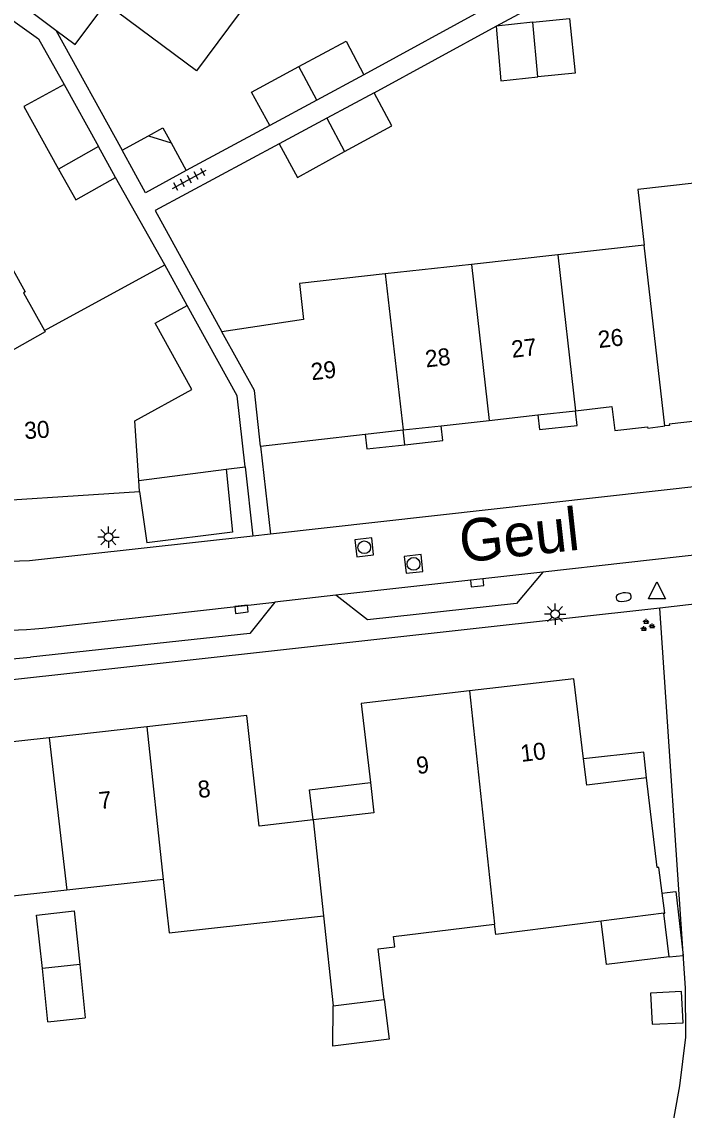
# Model space of a CAD drawing. Extents: x 131000 to 133013, y 393000 to 396501.
# Drawn here: x 131038.3 to 131077.2, y 394996 to 395059.9 of the extents above; entities that cross this region are included whole.
import ezdxf

# ---------------------------------------------------------------- set-up
doc = ezdxf.new("R2010")
doc.units = 0
for name, color, linetype in [('gg-afsc-erfafscheiding', 7, 'Continuous'), ('gg-afsc-muur', 7, 'Continuous'), ('gg-anno-huisnummerreeks BGT', 7, 'Continuous'), ('gg-anno-openbare ruimte label', 7, 'Continuous'), ('gg-bbg-bijgebouw', 7, 'Continuous'), ('gg-bbg-gedigitaliseerde bebouwing', 7, 'Continuous'), ('gg-bbg-gedigitaliseerde bijgebouw', 7, 'Continuous'), ('gg-bbg-hoofdgebouw', 7, 'Continuous'), ('gg-bbg-luifel en loopbrug', 7, 'Continuous'), ('gg-bbg-tussenscheiding', 7, 'Continuous'), ('gg-knt-verharding', 7, 'Continuous'), ('gg-knt-verharding nz', 7, 'Continuous'), ('gt-grn-weggrens', 7, 'Continuous'), ('gt-symb-brandkraan', 7, 'Continuous'), ('gt-symb-groenvak', 7, 'Continuous'), ('gt-symb-kolk', 7, 'Continuous'), ('gt-symb-lichtmast', 7, 'Continuous'), ('gt-symb-rioolschacht', 7, 'Continuous'), ('gt-symb-tegel verharding', 7, 'Continuous'), ('gt-symb-waterafsluiter', 7, 'Continuous')]:
    doc.layers.add(name, color=color, linetype=linetype)

# ---------------------------------------------------------------- blocks, each defined once
blk = doc.blocks.new('gt0-TEG1')
at = {"layer": 'gt-symb-tegel verharding'}
for p, q in [((-1.125, 0), (1.125, 0)), ((-0.9, -0.25), (-0.9, 0.25)), ((-0.45, -0.25), (-0.45, 0.25)), ((0, -0.25), (0, 0.25)), ((0.45, -0.25), (0.45, 0.25)), ((0.9, -0.25), (0.9, 0.25))]:
    blk.add_line(p, q, dxfattribs=at)
blk = doc.blocks.new('gt0-LMAST')
at = {"layer": 'gt-symb-lichtmast'}
for p, q in [((-0.182, 0.173), (-0.447, 0.438)), ((-0.005, 0.246), (-0.005, 0.621)), ((0.172, 0.173), (0.437, 0.438)), ((-0.255, -0.004), (-0.63, -0.004)), ((-0.182, -0.181), (-0.447, -0.446)), ((-0.005, -0.254), (-0.005, -0.629)), ((0.437, -0.446), (0.172, -0.181)), ((0.245, -0.004), (0.62, -0.004))]:
    blk.add_line(p, q, dxfattribs=at)
blk.add_circle((-0.005, -0.004), 0.25, dxfattribs=at)
blk = doc.blocks.new('gt0-KOLK')
at = {"layer": 'gt-symb-kolk'}
blk.add_lwpolyline([(0, 0), (0.375, 0), (0.375, 0.4), (-0.375, 0.4), (-0.375, 0), (0, 0)], dxfattribs=at)
blk = doc.blocks.new('gt0-GRVAK')
at = {"layer": 'gt-symb-groenvak'}
for p, q in [((-0.11, 0.189), (-0.228, 0.24)), ((-0.182, 0.153), (0.088, 0.153)), ((-0.091, 0.211), (-0.156, 0.322)), ((-0.047, 0.214), (-0.047, 0.393)), ((-0.004, 0.211), (0.061, 0.322)), ((0.015, 0.189), (0.133, 0.24)), ((0.262, -0.052), (0.197, 0.059)), ((0.305, -0.049), (0.305, 0.13)), ((0.349, -0.052), (0.414, 0.059)), ((-0.245, -0.228), (-0.363, -0.177)), ((-0.318, -0.264), (-0.047, -0.264)), ((-0.226, -0.206), (-0.291, -0.095)), ((-0.183, -0.203), (-0.183, -0.024)), ((-0.139, -0.206), (-0.074, -0.095)), ((-0.12, -0.228), (-0.002, -0.177)), ((0.243, -0.074), (0.125, -0.023)), ((0.17, -0.11), (0.441, -0.11)), ((0.368, -0.074), (0.486, -0.023))]:
    blk.add_line(p, q, dxfattribs=at)
blk = doc.blocks.new('gt0-BR')
at = {"layer": 'gt-symb-brandkraan'}
for centre, radius, start, end in [((-0.244, 0), 0.206, 107.56694, 252.43307), ((0.599, -2.664), 3, 106.89205, 107.56694), ((0, -0.691), 0.938, 73.10799, 106.89205), ((-0.599, -2.664), 3, 72.43309, 73.10799), ((0.244, 0), 0.206, 287.56695, 72.43309), ((0.599, 2.664), 3, 252.43307, 253.10797), ((0, 0.691), 0.938, 253.10797, 286.89206), ((-0.599, 2.664), 3, 286.89206, 287.56695)]:
    blk.add_arc(centre, radius, start, end, dxfattribs=at)
blk = doc.blocks.new('gt0-WAFSL')
at = {"layer": 'gt-symb-waterafsluiter'}
for p, q in [((-0.5, -0.333), (0, 0.667)), ((0, 0.667), (0.5, -0.333)), ((0.5, -0.333), (-0.5, -0.333))]:
    blk.add_line(p, q, dxfattribs=at)
blk = doc.blocks.new('gt0-RS')
at = {"layer": 'gt-symb-rioolschacht'}
blk.add_lwpolyline([(-0.5, -0.5), (0.5, -0.5), (0.5, 0.5), (-0.5, 0.5)], close=True, dxfattribs=at)
blk.add_circle((0, 0), 0.375, dxfattribs=at)

msp = doc.modelspace()

# ---------------------------------------------------------------- linework, layer by layer
at = {"layer": 'gg-afsc-erfafscheiding'}
for p, q in [((131066.17, 395059.68), (131073.198, 395063.476)), ((131065.77, 395060.86), (131058.4, 395056.83)), ((131058.99, 395055.77), (131066.17, 395059.68)), ((131040.288, 395059.456), (131044.182, 395052.388)), ((131052.86, 395053.84), (131047.957, 395051.193))]:
    msp.add_line(p, q, dxfattribs=at)
msp.add_lwpolyline([(131053.42, 395052.76), (131046.131, 395048.851), (131050.045, 395041.722)], dxfattribs=at)
at = {"layer": 'gg-afsc-muur'}
for p, q in [((131046.694, 395045.662), (131043.804, 395050.781)), ((131050.299, 395033.646), (131051.421, 395033.788))]:
    msp.add_line(p, q, dxfattribs=at)
for points in [[(131036.514, 395060.902), (131039.277, 395058.935), (131040.783, 395056.245)], [(131051.421, 395033.788), (131050.949, 395037.96), (131048.009, 395043.266)]]:
    msp.add_lwpolyline(points, dxfattribs=at)
at = {"layer": 'gg-bbg-bijgebouw'}
for p, q in [((131040.783, 395056.245), (131042.793, 395052.609)), ((131043.804, 395050.781), (131042.793, 395052.609)), ((131039.814, 395001.188), (131042.015, 395001.421))]:
    msp.add_line(p, q, dxfattribs=at)
for points in [[(131040.783, 395056.245), (131038.411, 395054.96), (131040.448, 395051.288)], [(131040.448, 395051.288), (131041.454, 395049.473), (131043.804, 395050.781)]]:
    msp.add_lwpolyline(points, dxfattribs=at)
at = {"layer": 'gg-bbg-gedigitaliseerde bebouwing'}
for p, q in [((131048.546, 395057.049), (131043.22, 395061.013)), ((131051.699, 395061.284), (131048.546, 395057.049)), ((131069.79, 395046.246), (131064.721, 395045.685)), ((131074.86, 395046.807), (131069.79, 395046.246)), ((131039.62, 395041.81), (131046.694, 395045.662)), ((131064.721, 395045.685), (131059.651, 395045.125)), ((131055.407, 395013.049), (131052.245, 395012.679)), ((131056.017, 395007.422), (131056.591, 395002.127)), ((131076.019, 395007.561), (131072.334, 395007.097)), ((131056.591, 395002.127), (131059.591, 395002.494))]:
    msp.add_line(p, q, dxfattribs=at)
for points in [[(131079.558, 395050.644), (131074.498, 395050.085), (131074.86, 395046.807)], [(131034.95, 395047.97), (131036.74, 395044.76), (131037.78, 395045.34), (131038.49, 395044.07), (131038.39, 395044.02), (131039.62, 395041.81)], [(131059.651, 395045.125), (131054.616, 395044.568), (131054.85, 395042.443), (131050.045, 395041.722)], [(131046.602, 395009.545), (131046.941, 395006.416), (131056.017, 395007.422)], [(131059.591, 395002.494), (131059.227, 395005.473), (131060.212, 395005.593), (131060.137, 395006.204), (131066.075, 395006.929)], [(131072.334, 395007.097), (131066.143, 395006.317), (131066.075, 395006.929)]]:
    msp.add_lwpolyline(points, dxfattribs=at)
at = {"layer": 'gg-bbg-gedigitaliseerde bijgebouw'}
for p, q in [((131068.32, 395059.909), (131066.17, 395059.68)), ((131058.4, 395056.83), (131055.628, 395055.334)), ((131055.628, 395055.334), (131052.86, 395053.84)), ((131058.99, 395055.77), (131056.214, 395054.27)), ((131056.214, 395054.27), (131053.42, 395052.76)), ((131044.182, 395052.388), (131045.728, 395053.241)), ((131045.728, 395053.241), (131047.061, 395052.819)), ((131047.061, 395052.819), (131047.957, 395051.193)), ((131039.814, 395001.188), (131039.504, 395004.309)), ((131041.705, 395004.545), (131042.015, 395001.421))]:
    msp.add_line(p, q, dxfattribs=at)
for points in [[(131066.17, 395059.68), (131066.45, 395056.47), (131068.62, 395056.699)], [(131068.32, 395059.909), (131070.48, 395060.14), (131070.81, 395056.93), (131068.62, 395056.699)], [(131054.57, 395057.31), (131057.36, 395058.8), (131058.4, 395056.83)], [(131052.86, 395053.84), (131051.78, 395055.81), (131054.57, 395057.31)], [(131057.261, 395052.311), (131060.03, 395053.82), (131058.99, 395055.77)], [(131053.42, 395052.76), (131054.49, 395050.8), (131057.261, 395052.311)], [(131047.957, 395051.193), (131045.557, 395049.898), (131044.182, 395052.388)], [(131039.504, 395004.309), (131039.16, 395007.46), (131041.36, 395007.7), (131041.705, 395004.545)]]:
    msp.add_lwpolyline(points, dxfattribs=at)
at = {"layer": 'gg-bbg-hoofdgebouw'}
for p, q in [((131035.868, 395062.773), (131040.288, 395059.456)), ((131048.009, 395043.266), (131046.694, 395045.662)), ((131065.762, 395036.523), (131068.609, 395036.842)), ((131068.609, 395036.842), (131070.839, 395037.091)), ((131060.698, 395035.957), (131062.928, 395036.206)), ((131062.928, 395036.206), (131065.762, 395036.523)), ((131052.322, 395035.015), (131058.469, 395035.706)), ((131058.469, 395035.706), (131060.698, 395035.957)), ((131045.205, 395032.349), (131045.163, 395032.996)), ((131045.629, 395018.516), (131039.895, 395017.875)), ((131039.895, 395017.875), (131034.286, 395017.25)), ((131046.602, 395009.545), (131040.936, 395008.917)), ((131040.936, 395008.917), (131035.273, 395008.289))]:
    msp.add_line(p, q, dxfattribs=at)
for points in [[(131040.288, 395059.456), (131041.427, 395058.607), (131043.22, 395061.013)], [(131045.163, 395032.996), (131044.938, 395036.497), (131048.291, 395038.341), (131046.122, 395042.23), (131048.009, 395043.266)], [(131052.322, 395035.015), (131051.956, 395038.268), (131050.045, 395041.722)], [(131080.967, 395038.233), (131078.768, 395037.987), (131078.924, 395036.587), (131076.34, 395036.298), (131076.348, 395036.222), (131076.076, 395036.192)], [(131070.839, 395037.091), (131072.966, 395037.329), (131073.139, 395035.92), (131075.064, 395036.148), (131075.077, 395036.073), (131075.971, 395036.18), (131076.076, 395036.192)], [(131029.037, 395035.608), (131031.141, 395032.126), (131033.704, 395032.319), (131033.763, 395031.606), (131045.205, 395032.349)], [(131071.309, 395016.639), (131070.735, 395021.344), (131064.605, 395020.628)], [(131064.605, 395020.628), (131058.233, 395019.883), (131058.776, 395015.242)], [(131052.245, 395012.679), (131051.523, 395019.173), (131045.629, 395018.516)], [(131075.012, 395015.521), (131071.498, 395015.092), (131071.309, 395016.639)], [(131058.776, 395015.242), (131058.983, 395013.467), (131055.407, 395013.049)], [(131075.924, 395008.752), (131075.735, 395010.258), (131075.635, 395010.246), (131075.012, 395015.521)], [(131076.019, 395007.561), (131076.072, 395007.568), (131075.924, 395008.752)]]:
    msp.add_lwpolyline(points, dxfattribs=at)
at = {"layer": 'gg-bbg-luifel en loopbrug'}
for p, q in [((131060.795, 395035.094), (131060.698, 395035.957)), ((131045.163, 395032.996), (131050.299, 395033.646)), ((131045.205, 395032.349), (131045.633, 395029.32)), ((131076.332, 395005), (131076.019, 395007.561)), ((131076.332, 395005), (131077.151, 395005.091))]:
    msp.add_line(p, q, dxfattribs=at)
for points in [[(131045.728, 395053.241), (131046.573, 395053.706), (131047.061, 395052.819)], [(131068.609, 395036.842), (131068.707, 395035.978), (131070.936, 395036.229), (131070.839, 395037.091)], [(131060.795, 395035.094), (131063.024, 395035.344), (131062.928, 395036.206)], [(131058.469, 395035.706), (131058.566, 395034.843), (131060.795, 395035.094)], [(131050.299, 395033.646), (131050.665, 395029.962), (131045.633, 395029.32)], [(131075.012, 395015.521), (131074.844, 395017.033), (131071.309, 395016.639)], [(131055.407, 395013.049), (131055.2, 395014.824), (131058.776, 395015.242)], [(131075.924, 395008.752), (131076.215, 395008.784), (131076.733, 395008.842), (131077.151, 395005.091)], [(131076.332, 395005), (131072.645, 395004.55), (131072.334, 395007.097)], [(131077.067, 395002.966), (131075.235, 395002.87), (131075.33, 395001.039), (131077.162, 395001.134), (131077.067, 395002.966)], [(131059.591, 395002.494), (131059.875, 395000.167), (131056.575, 394999.764), (131056.591, 395002.127)]]:
    msp.add_lwpolyline(points, dxfattribs=at)
at = {"layer": 'gg-bbg-tussenscheiding'}
for p, q in [((131068.62, 395056.699), (131068.32, 395059.909)), ((131055.628, 395055.334), (131054.57, 395057.31)), ((131056.214, 395054.27), (131057.261, 395052.311)), ((131042.793, 395052.609), (131040.448, 395051.288)), ((131069.79, 395046.246), (131070.839, 395037.091)), ((131076.076, 395036.192), (131074.86, 395046.807)), ((131064.721, 395045.685), (131065.762, 395036.523)), ((131059.651, 395045.125), (131060.698, 395035.957)), ((131064.605, 395020.628), (131066.075, 395006.929)), ((131045.629, 395018.516), (131046.602, 395009.545)), ((131039.895, 395017.875), (131040.936, 395008.917)), ((131055.407, 395013.049), (131056.017, 395007.422)), ((131041.705, 395004.545), (131039.504, 395004.309))]:
    msp.add_line(p, q, dxfattribs=at)
msp.add_lwpolyline([(131039.62, 395041.81), (131039.66, 395041.73), (131032.44, 395037.65), (131032.52, 395037.5), (131029.037, 395035.608)], dxfattribs=at)
at = {"layer": 'gg-knt-verharding'}
for p, q in [((131052.322, 395035.015), (131052.904, 395029.843)), ((131051.421, 395033.788), (131051.875, 395029.728)), ((131089.935, 395033.973), (131052.904, 395029.843)), ((131052.904, 395029.843), (131051.875, 395029.728)), ((131084.087, 395029.312), (131068.918, 395027.612)), ((131056.748, 395026.248), (131053.169, 395025.845)), ((131075.79, 395025.482), (131020.631, 395019.388))]:
    msp.add_line(p, q, dxfattribs=at)
for points in [[(131051.875, 395029.728), (131038.745, 395028.264), (131036.348, 395028.2), (131033.974, 395028.54)], [(131068.918, 395027.612), (131067.36, 395025.757), (131058.597, 395024.801), (131056.748, 395026.248)], [(131053.169, 395025.845), (131051.686, 395023.998), (131038.805, 395022.609)], [(131074.984, 394986.167), (131075.24, 394987.881), (131076.97, 394997.423), (131077.307, 395000.28), (131077.291, 395003.156), (131075.79, 395025.482)]]:
    msp.add_lwpolyline(points, dxfattribs=at)
msp.add_arc((131036.63, 395042.777), 20.285, 237.39408, 276.15607, dxfattribs=at)
at = {"layer": 'gg-knt-verharding nz'}
for p, q in [((131068.918, 395027.612), (131056.748, 395026.248)), ((131039.525, 395024.316), (131053.169, 395025.845))]:
    msp.add_line(p, q, dxfattribs=at)
msp.add_arc((131037.228, 395045.177), 20.987, 234.90218, 276.28321, dxfattribs=at)
at = {"layer": 'gt-grn-weggrens'}
msp.add_line((131078.322, 395025.784), (131075.79, 395025.482), dxfattribs=at)

# ---------------------------------------------------------------- block references
at = {"layer": 'gt-symb-brandkraan', "rotation": 6.371822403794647}
msp.add_blockref('gt0-BR', (131073.663, 395026.137), dxfattribs=at)
at = {"layer": 'gt-symb-groenvak'}
msp.add_blockref('gt0-GRVAK', (131075.032, 395024.462), dxfattribs=at)
at = {"layer": 'gt-symb-kolk'}
for p, rotation in [((131065.072, 395026.78), 6.200970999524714), ((131051.181, 395025.621), -173.62817759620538)]:
    msp.add_blockref('gt0-KOLK', p, dxfattribs=dict(at, rotation=rotation))
at = {"layer": 'gt-symb-lichtmast'}
for p in [(131043.387, 395029.665), (131069.638, 395025.144)]:
    msp.add_blockref('gt0-LMAST', p, dxfattribs=at)
at = {"layer": 'gt-symb-rioolschacht'}
for p, rotation in [((131058.415, 395029.066), 6.371822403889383), ((131061.311, 395028.091), 6.371822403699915)]:
    msp.add_blockref('gt0-RS', p, dxfattribs=dict(at, rotation=rotation))
at = {"layer": 'gt-symb-tegel verharding', "rotation": 28.203821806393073}
msp.add_blockref('gt0-TEG1', (131048.136, 395050.681), dxfattribs=at)
at = {"layer": 'gt-symb-waterafsluiter'}
msp.add_blockref('gt0-WAFSL', (131075.614, 395026.361), dxfattribs=at)

# ---------------------------------------------------------------- texts
at = {"layer": 'gg-anno-huisnummerreeks BGT'}
for s, rotation, p in [('26', 6.4, (131072.208, 395040.768)), ('27', 6.4, (131067.117, 395040.196)), ('28', 6.4, (131062.051, 395039.629)), ('29', 6.4, (131055.333, 395038.875)), ('30', 3.7, (131038.464, 395035.419)), ('10', 6.7, (131067.655, 395016.452)), ('9', 6.7, (131061.533, 395015.738)), ('8', 6.4, (131048.688, 395014.329)), ('7', 6.4, (131042.875, 395013.68))]:
    msp.add_text(s, height=1, rotation=rotation, dxfattribs=at).set_placement(p)
at = {"layer": 'gg-anno-openbare ruimte label'}
msp.add_text('Geul', height=2.5, rotation=6.3, dxfattribs=at).set_placement((131064.136, 395028.156))

doc.saveas('drawing.dxf')
